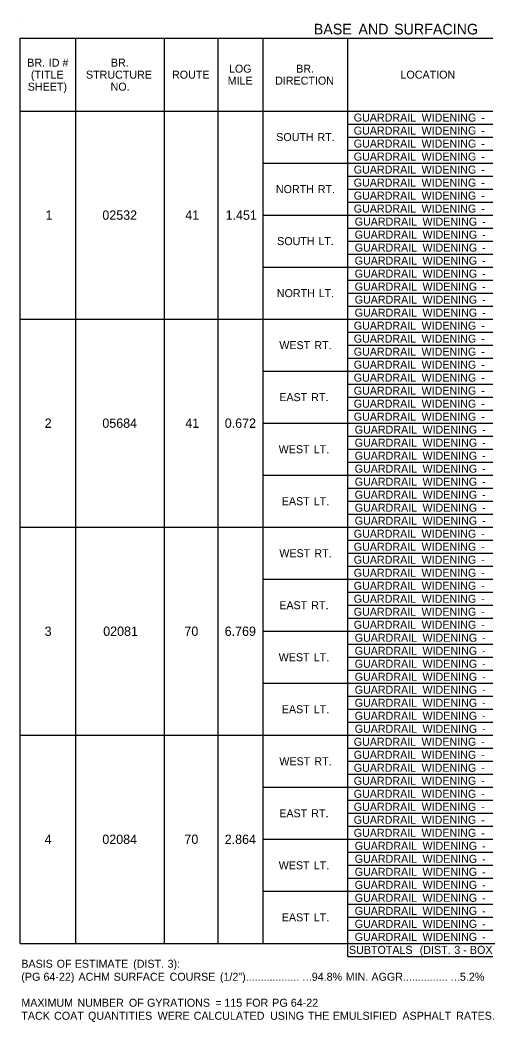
# Model space of a CAD drawing. Extents: x 544478 to 1930787, y -1948294 to 596640.
# Drawn here: x 550258 to 550607, y -1946930 to -1946179 of the extents above; entities that cross this region are included whole.
import ezdxf

# ---------------------------------------------------------------- set-up
doc = ezdxf.new("R2010")
doc.units = 0
doc.layers.add('Default', color=7, linetype='Continuous')

msp = doc.modelspace()

# ---------------------------------------------------------------- linework, layer by layer
at = {"layer": 'Default'}
for p, q in [((550257.56, -1946178.84), (550257.56, -1946178.84)), ((550257.56, -1946192.49), (551079.97, -1946192.49)), ((550257.56, -1946871.09), (550257.56, -1946192.49)), ((550299.48, -1946247.09), (550299.48, -1946192.49)), ((550299.48, -1946871.09), (550299.48, -1946192.49)), ((550365.78, -1946871.09), (550365.78, -1946192.49)), ((550406.25, -1946871.09), (550406.25, -1946192.49)), ((550439.88, -1946871.09), (550439.88, -1946192.49)), ((550503.26, -1946880.84), (550503.26, -1946192.49)), ((550257.56, -1946247.09), (551079.97, -1946247.09)), ((550503.26, -1946256.84), (551079.97, -1946256.84)), ((550503.26, -1946266.59), (551079.97, -1946266.59)), ((550503.26, -1946276.34), (551079.97, -1946276.34)), ((550439.88, -1946286.09), (550503.26, -1946286.09)), ((550503.26, -1946286.09), (551079.97, -1946286.09)), ((550503.26, -1946295.84), (551079.97, -1946295.84)), ((550503.26, -1946305.59), (551079.97, -1946305.59)), ((550503.26, -1946315.34), (551079.97, -1946315.34)), ((550439.88, -1946325.09), (550503.26, -1946325.09)), ((550503.26, -1946325.09), (551079.97, -1946325.09)), ((550503.26, -1946334.84), (551079.97, -1946334.84)), ((550503.26, -1946344.59), (551079.97, -1946344.59)), ((550503.26, -1946354.34), (551079.97, -1946354.34)), ((550439.88, -1946364.09), (550503.26, -1946364.09)), ((550503.26, -1946364.09), (550777.23, -1946364.09)), ((550503.26, -1946373.84), (551079.97, -1946373.84)), ((550503.26, -1946383.59), (550777.23, -1946383.59)), ((550503.26, -1946393.34), (550777.23, -1946393.34)), ((550257.56, -1946403.09), (551079.97, -1946403.09)), ((550503.26, -1946412.84), (551079.97, -1946412.84)), ((550503.26, -1946422.59), (551079.97, -1946422.59)), ((550503.26, -1946432.34), (551079.97, -1946432.34)), ((550439.88, -1946442.09), (550503.26, -1946442.09)), ((550503.26, -1946442.09), (551079.97, -1946442.09)), ((550503.26, -1946451.84), (551079.97, -1946451.84)), ((550503.26, -1946461.59), (551079.97, -1946461.59)), ((550503.26, -1946471.34), (551079.97, -1946471.34)), ((550439.88, -1946481.09), (550503.26, -1946481.09)), ((550503.26, -1946481.09), (551079.97, -1946481.09)), ((550503.26, -1946490.84), (551079.97, -1946490.84)), ((550503.26, -1946500.59), (551079.97, -1946500.59)), ((550503.26, -1946510.34), (551079.97, -1946510.34)), ((550439.88, -1946520.09), (550503.26, -1946520.09)), ((550503.26, -1946520.09), (550777.23, -1946520.09)), ((550503.26, -1946529.84), (551079.97, -1946529.84)), ((550503.26, -1946539.59), (550777.23, -1946539.59)), ((550503.26, -1946549.34), (550777.23, -1946549.34)), ((550257.56, -1946559.09), (551079.97, -1946559.09)), ((550503.26, -1946568.84), (551079.97, -1946568.84)), ((550503.26, -1946578.59), (551079.97, -1946578.59)), ((550503.26, -1946588.34), (551079.97, -1946588.34)), ((550439.88, -1946598.09), (550503.26, -1946598.09)), ((550503.26, -1946598.09), (551079.97, -1946598.09)), ((550503.26, -1946607.84), (551079.97, -1946607.84)), ((550503.26, -1946617.59), (551079.97, -1946617.59)), ((550503.26, -1946627.34), (551079.97, -1946627.34)), ((550439.88, -1946637.09), (550503.26, -1946637.09)), ((550503.26, -1946637.09), (551079.97, -1946637.09)), ((550503.26, -1946646.84), (551079.97, -1946646.84)), ((550503.26, -1946656.59), (551079.97, -1946656.59)), ((550503.26, -1946666.34), (551079.97, -1946666.34)), ((550439.88, -1946676.09), (550503.26, -1946676.09)), ((550503.26, -1946676.09), (550777.23, -1946676.09)), ((550503.26, -1946685.84), (551079.97, -1946685.84)), ((550503.26, -1946695.59), (550777.23, -1946695.59)), ((550503.26, -1946705.34), (550777.23, -1946705.34)), ((550257.56, -1946715.09), (551079.97, -1946715.09)), ((550503.26, -1946724.84), (551079.97, -1946724.84)), ((550503.26, -1946734.59), (551079.97, -1946734.59)), ((550503.26, -1946744.34), (551079.97, -1946744.34)), ((550439.88, -1946754.09), (550503.26, -1946754.09)), ((550503.26, -1946754.09), (551079.97, -1946754.09)), ((550503.26, -1946763.84), (551079.97, -1946763.84)), ((550503.26, -1946773.59), (551079.97, -1946773.59)), ((550503.26, -1946783.34), (551079.97, -1946783.34)), ((550439.88, -1946793.09), (550503.26, -1946793.09)), ((550503.26, -1946793.09), (551079.97, -1946793.09)), ((550503.26, -1946802.84), (551079.97, -1946802.84)), ((550503.26, -1946812.59), (551079.97, -1946812.59)), ((550503.26, -1946822.34), (551079.97, -1946822.34)), ((550439.88, -1946832.09), (550503.26, -1946832.09)), ((550503.26, -1946832.09), (550777.23, -1946832.09)), ((550503.26, -1946841.84), (551079.97, -1946841.84)), ((550503.26, -1946851.59), (550777.23, -1946851.59)), ((550503.26, -1946861.34), (550777.23, -1946861.34)), ((550257.56, -1946871.09), (551079.97, -1946871.09)), ((550503.26, -1946880.84), (550503.26, -1946871.09)), ((550503.26, -1946880.84), (551079.97, -1946880.84))]:
    msp.add_line(p, q, dxfattribs=at)

# ---------------------------------------------------------------- texts
for s, height, p in [('BASE', 8, (550477.82, -1946189.67)), (' AND', 8, (550508.32, -1946189.67)), (' SURFACING', 8, (550535.09, -1946189.67)), ('BR.', 6, (550263, -1946213.79)), (' ID', 6, (550276.86, -1946213.79)), (' #', 6, (550287.15, -1946213.79)), ('BR.', 6, (550325.7, -1946213.79)), ('(TITLE', 6, (550265.69, -1946222.79)), ('STRUCTURE', 6, (550306.99, -1946222.79)), ('ROUTE', 6, (550371.55, -1946222.79)), ('LOG', 6, (550414.24, -1946218.29)), ('BR.', 6, (550464.64, -1946218.29)), ('LOCATION', 6, (550542.89, -1946222.79)), ('SHEET)', 6, (550263.37, -1946231.79)), ('NO.', 6, (550325.47, -1946231.79)), ('MILE', 6, (550413.26, -1946227.29)), ('DIRECTION', 6, (550448.85, -1946227.29)), ('GUARDRAIL', 6, (550507.83, -1946254.97)), (' WIDENING', 6, (550556.45, -1946254.97)), (' -', 6, (550601.09, -1946254.97)), ('SOUTH', 6, (550449.69, -1946269.59)), (' RT.', 6, (550478.36, -1946269.59)), ('GUARDRAIL', 6, (550507.83, -1946264.72)), (' WIDENING', 6, (550556.45, -1946264.72)), (' -', 6, (550601.09, -1946264.72)), ('GUARDRAIL', 6, (550507.83, -1946274.47)), (' WIDENING', 6, (550556.45, -1946274.47)), ('GUARDRAIL', 6, (550507.83, -1946284.22)), (' WIDENING', 6, (550556.45, -1946284.22)), (' -', 6, (550601.09, -1946274.47)), (' -', 6, (550601.09, -1946284.22)), ('GUARDRAIL', 6, (550507.83, -1946293.97)), (' WIDENING', 6, (550556.45, -1946293.97)), (' -', 6, (550601.09, -1946293.97)), ('GUARDRAIL', 6, (550507.83, -1946303.72)), (' WIDENING', 6, (550556.45, -1946303.72)), (' -', 6, (550601.09, -1946303.72)), ('NORTH', 6, (550449.46, -1946308.59)), (' RT.', 6, (550478.59, -1946308.59)), ('GUARDRAIL', 6, (550507.83, -1946313.47)), (' WIDENING', 6, (550556.45, -1946313.47)), (' -', 6, (550601.09, -1946313.47)), ('1', 7, (550276.7, -1946328.59)), ('02532', 7, (550319.3, -1946328.59)), ('41', 7, (550381.48, -1946328.59)), ('1.451', 7, (550411.73, -1946328.59)), ('GUARDRAIL', 6, (550507.83, -1946323.22)), (' WIDENING', 6, (550556.45, -1946323.22)), (' -', 6, (550601.09, -1946323.22)), ('GUARDRAIL', 6, (550508.53, -1946332.97)), (' WIDENING', 6, (550557.14, -1946332.97)), (' -', 6, (550601.79, -1946332.97)), ('GUARDRAIL', 6, (550508.53, -1946342.72)), (' WIDENING', 6, (550557.14, -1946342.72)), ('SOUTH', 6, (550450.38, -1946347.59)), (' LT.', 6, (550479.05, -1946347.59)), ('GUARDRAIL', 6, (550508.53, -1946352.47)), (' WIDENING', 6, (550557.14, -1946352.47)), (' -', 6, (550601.79, -1946342.72)), (' -', 6, (550601.79, -1946352.47)), ('GUARDRAIL', 6, (550508.53, -1946362.22)), (' WIDENING', 6, (550557.14, -1946362.22)), (' -', 6, (550601.79, -1946362.22)), ('GUARDRAIL', 6, (550508.53, -1946371.97)), (' WIDENING', 6, (550557.14, -1946371.97)), ('GUARDRAIL', 6, (550508.53, -1946381.72)), (' WIDENING', 6, (550557.14, -1946381.72)), (' -', 6, (550601.79, -1946371.97)), ('NORTH', 6, (550450.15, -1946386.59)), (' LT.', 6, (550479.28, -1946386.59)), (' -', 6, (550601.79, -1946381.72)), ('GUARDRAIL', 6, (550508.53, -1946391.47)), (' WIDENING', 6, (550557.14, -1946391.47)), (' -', 6, (550601.79, -1946391.47)), ('GUARDRAIL', 6, (550508.53, -1946401.22)), (' WIDENING', 6, (550557.14, -1946401.22)), (' -', 6, (550601.79, -1946401.22)), ('GUARDRAIL', 6, (550507.83, -1946410.97)), (' WIDENING', 6, (550556.45, -1946410.97)), (' -', 6, (550601.09, -1946410.97)), ('WEST', 6, (550452, -1946425.59)), (' RT.', 6, (550476.05, -1946425.59)), ('GUARDRAIL', 6, (550507.83, -1946420.72)), (' WIDENING', 6, (550556.45, -1946420.72)), (' -', 6, (550601.09, -1946420.72)), ('GUARDRAIL', 6, (550507.83, -1946430.47)), (' WIDENING', 6, (550556.45, -1946430.47)), (' -', 6, (550601.09, -1946430.47)), ('GUARDRAIL', 6, (550507.83, -1946440.22)), (' WIDENING', 6, (550556.45, -1946440.22)), ('GUARDRAIL', 6, (550507.83, -1946449.97)), (' WIDENING', 6, (550556.45, -1946449.97)), (' -', 6, (550601.09, -1946440.22)), (' -', 6, (550601.09, -1946449.97)), ('EAST', 6, (550451.99, -1946464.59)), (' RT.', 6, (550473.72, -1946464.59)), ('GUARDRAIL', 6, (550507.83, -1946459.72)), (' WIDENING', 6, (550556.45, -1946459.72)), (' -', 6, (550601.09, -1946459.72)), ('GUARDRAIL', 6, (550507.83, -1946469.47)), (' WIDENING', 6, (550556.45, -1946469.47)), ('GUARDRAIL', 6, (550507.83, -1946479.22)), (' WIDENING', 6, (550556.45, -1946479.22)), (' -', 6, (550601.09, -1946469.47)), ('2', 7, (550276.06, -1946484.59)), ('05684', 7, (550319.28, -1946484.59)), ('41', 7, (550381.48, -1946484.59)), ('0.672', 7, (550411.09, -1946484.59)), (' -', 6, (550601.09, -1946479.22)), ('GUARDRAIL', 6, (550508.53, -1946488.97)), (' WIDENING', 6, (550557.14, -1946488.97)), (' -', 6, (550601.79, -1946488.97)), ('GUARDRAIL', 6, (550508.53, -1946498.72)), (' WIDENING', 6, (550557.14, -1946498.72)), (' -', 6, (550601.79, -1946498.72)), ('WEST', 6, (550451.53, -1946503.59)), (' LT.', 6, (550475.58, -1946503.59)), ('GUARDRAIL', 6, (550508.53, -1946508.47)), (' WIDENING', 6, (550557.14, -1946508.47)), (' -', 6, (550601.79, -1946508.47)), ('GUARDRAIL', 6, (550508.53, -1946518.22)), (' WIDENING', 6, (550557.14, -1946518.22)), (' -', 6, (550601.79, -1946518.22)), ('GUARDRAIL', 6, (550508.53, -1946527.97)), (' WIDENING', 6, (550557.14, -1946527.97)), (' -', 6, (550601.79, -1946527.97)), ('GUARDRAIL', 6, (550508.53, -1946537.72)), (' WIDENING', 6, (550557.14, -1946537.72)), ('EAST', 6, (550453.85, -1946542.59)), (' LT.', 6, (550475.59, -1946542.59)), ('GUARDRAIL', 6, (550508.53, -1946547.47)), (' WIDENING', 6, (550557.14, -1946547.47)), (' -', 6, (550601.79, -1946537.72)), (' -', 6, (550601.79, -1946547.47)), ('GUARDRAIL', 6, (550508.53, -1946557.22)), (' WIDENING', 6, (550557.14, -1946557.22)), (' -', 6, (550601.79, -1946557.22)), ('GUARDRAIL', 6, (550507.83, -1946566.97)), (' WIDENING', 6, (550556.45, -1946566.97)), ('GUARDRAIL', 6, (550507.83, -1946576.72)), (' WIDENING', 6, (550556.45, -1946576.72)), (' -', 6, (550601.09, -1946566.97)), ('WEST', 6, (550452, -1946581.59)), (' RT.', 6, (550476.05, -1946581.59)), (' -', 6, (550601.09, -1946576.72)), ('GUARDRAIL', 6, (550507.83, -1946586.47)), (' WIDENING', 6, (550556.45, -1946586.47)), (' -', 6, (550601.09, -1946586.47)), ('GUARDRAIL', 6, (550507.83, -1946596.22)), (' WIDENING', 6, (550556.45, -1946596.22)), (' -', 6, (550601.09, -1946596.22)), ('GUARDRAIL', 6, (550507.83, -1946605.97)), (' WIDENING', 6, (550556.45, -1946605.97)), (' -', 6, (550601.09, -1946605.97)), ('EAST', 6, (550451.99, -1946620.59)), (' RT.', 6, (550473.72, -1946620.59)), ('GUARDRAIL', 6, (550507.83, -1946615.72)), (' WIDENING', 6, (550556.45, -1946615.72)), (' -', 6, (550601.09, -1946615.72)), ('GUARDRAIL', 6, (550507.83, -1946625.47)), (' WIDENING', 6, (550556.45, -1946625.47)), (' -', 6, (550601.09, -1946625.47)), ('GUARDRAIL', 6, (550507.83, -1946635.22)), (' WIDENING', 6, (550556.45, -1946635.22)), ('3', 7, (550276.03, -1946640.59)), ('02081', 7, (550319.94, -1946640.59)), ('70', 7, (550380.81, -1946640.59)), ('6.769', 7, (550411.05, -1946640.59)), ('GUARDRAIL', 6, (550508.53, -1946644.97)), (' WIDENING', 6, (550557.14, -1946644.97)), (' -', 6, (550601.09, -1946635.22)), (' -', 6, (550601.79, -1946644.97)), ('WEST', 6, (550451.53, -1946659.59)), (' LT.', 6, (550475.58, -1946659.59)), ('GUARDRAIL', 6, (550508.53, -1946654.72)), (' WIDENING', 6, (550557.14, -1946654.72)), (' -', 6, (550601.79, -1946654.72)), ('GUARDRAIL', 6, (550508.53, -1946664.47)), (' WIDENING', 6, (550557.14, -1946664.47)), (' -', 6, (550601.79, -1946664.47)), ('GUARDRAIL', 6, (550508.53, -1946674.22)), (' WIDENING', 6, (550557.14, -1946674.22)), (' -', 6, (550601.79, -1946674.22)), ('GUARDRAIL', 6, (550508.53, -1946683.97)), (' WIDENING', 6, (550557.14, -1946683.97)), (' -', 6, (550601.79, -1946683.97)), ('GUARDRAIL', 6, (550508.53, -1946693.72)), (' WIDENING', 6, (550557.14, -1946693.72)), (' -', 6, (550601.79, -1946693.72)), ('EAST', 6, (550453.85, -1946698.59)), (' LT.', 6, (550475.59, -1946698.59)), ('GUARDRAIL', 6, (550508.53, -1946703.47)), (' WIDENING', 6, (550557.14, -1946703.47)), (' -', 6, (550601.79, -1946703.47)), ('GUARDRAIL', 6, (550508.53, -1946713.22)), (' WIDENING', 6, (550557.14, -1946713.22)), (' -', 6, (550601.79, -1946713.22)), ('GUARDRAIL', 6, (550507.83, -1946722.97)), (' WIDENING', 6, (550556.45, -1946722.97)), (' -', 6, (550601.09, -1946722.97)), ('GUARDRAIL', 6, (550507.83, -1946732.72)), (' WIDENING', 6, (550556.45, -1946732.72)), ('WEST', 6, (550452, -1946737.59)), (' RT.', 6, (550476.05, -1946737.59)), ('GUARDRAIL', 6, (550507.83, -1946742.47)), (' WIDENING', 6, (550556.45, -1946742.47)), (' -', 6, (550601.09, -1946732.72)), (' -', 6, (550601.09, -1946742.47)), ('GUARDRAIL', 6, (550507.83, -1946752.22)), (' WIDENING', 6, (550556.45, -1946752.22)), (' -', 6, (550601.09, -1946752.22)), ('GUARDRAIL', 6, (550507.83, -1946761.97)), (' WIDENING', 6, (550556.45, -1946761.97)), (' -', 6, (550601.09, -1946761.97)), ('GUARDRAIL', 6, (550507.83, -1946771.72)), (' WIDENING', 6, (550556.45, -1946771.72)), ('EAST', 6, (550451.99, -1946776.59)), (' RT.', 6, (550473.72, -1946776.59)), (' -', 6, (550601.09, -1946771.72)), ('GUARDRAIL', 6, (550507.83, -1946781.47)), (' WIDENING', 6, (550556.45, -1946781.47)), (' -', 6, (550601.09, -1946781.47)), ('4', 7, (550276.04, -1946796.59)), ('02084', 7, (550319.28, -1946796.59)), ('70', 7, (550380.81, -1946796.59)), ('2.864', 7, (550411.07, -1946796.59)), ('GUARDRAIL', 6, (550507.83, -1946791.22)), (' WIDENING', 6, (550556.45, -1946791.22)), (' -', 6, (550601.09, -1946791.22)), ('GUARDRAIL', 6, (550508.53, -1946800.97)), (' WIDENING', 6, (550557.14, -1946800.97)), ('GUARDRAIL', 6, (550508.53, -1946810.72)), (' WIDENING', 6, (550557.14, -1946810.72)), (' -', 6, (550601.79, -1946800.97)), ('WEST', 6, (550451.53, -1946815.59)), (' LT.', 6, (550475.58, -1946815.59)), (' -', 6, (550601.79, -1946810.72)), ('GUARDRAIL', 6, (550508.53, -1946820.47)), (' WIDENING', 6, (550557.14, -1946820.47)), (' -', 6, (550601.79, -1946820.47)), ('GUARDRAIL', 6, (550508.53, -1946830.22)), (' WIDENING', 6, (550557.14, -1946830.22)), ('GUARDRAIL', 6, (550508.53, -1946839.97)), (' WIDENING', 6, (550557.14, -1946839.97)), (' -', 6, (550601.79, -1946830.22)), (' -', 6, (550601.79, -1946839.97)), ('EAST', 6, (550453.85, -1946854.59)), (' LT.', 6, (550475.59, -1946854.59)), ('GUARDRAIL', 6, (550508.53, -1946849.72)), (' WIDENING', 6, (550557.14, -1946849.72)), (' -', 6, (550601.79, -1946849.72)), ('GUARDRAIL', 6, (550508.53, -1946859.47)), (' WIDENING', 6, (550557.14, -1946859.47)), (' -', 6, (550601.79, -1946859.47)), ('GUARDRAIL', 6, (550508.53, -1946869.22)), (' WIDENING', 6, (550557.14, -1946869.22)), (' -', 6, (550601.79, -1946869.22)), ('SUBTOTALS', 6, (550504.23, -1946878.97)), (' (DIST.', 6, (550555.06, -1946878.97)), (' 3', 6, (550581.03, -1946878.97)), (' -', 6, (550587.65, -1946878.97)), (' BOX', 6, (550592.71, -1946878.97)), ('BASIS', 6, (550258.53, -1946889.39)), (' OF', 6, (550282.8, -1946889.39)), (' ESTIMATE', 6, (550296.38, -1946889.39)), (' (DIST.', 6, (550340.19, -1946889.39)), (' 3):', 6, (550366, -1946889.39)), ('(PG', 6, (550258.53, -1946899.14)), (' 64-22)', 6, (550272.91, -1946899.14)), (' ACHM', 6, (550299.16, -1946899.14)), (' SURFACE', 6, (550325.54, -1946899.14)), (' COURSE', 6, (550367.49, -1946899.14)), (' (1/2")..................', 6, (550405.24, -1946899.14)), ('94.8%', 6, (550476.34, -1946899.14)), (' MIN.', 6, (550499.58, -1946899.14)), (' AGGR...............', 6, (550518.87, -1946899.14)), ('5.2%', 6, (550587.47, -1946899.14)), ('…', 6, (550468.94, -1946899.14)), ('…', 6, (550580.07, -1946899.14)), ('MAXIMUM', 6, (550258.53, -1946918.64)), (' NUMBER', 6, (550298.42, -1946918.64)), (' OF', 6, (550336.97, -1946918.64)), (' GYRATIONS', 6, (550350.56, -1946918.64)), (' =', 6, (550401.83, -1946918.64)), (' 115', 6, (550408.58, -1946918.64)), (' FOR', 6, (550424.55, -1946918.64)), (' PG', 6, (550444.47, -1946918.64)), (' 64-22', 6, (550458.38, -1946918.64)), ('TACK', 6, (550258.53, -1946928.39)), (' COAT', 6, (550280.88, -1946928.39)), (' QUANTITIES', 6, (550306.33, -1946928.39)), (' WERE', 6, (550358.53, -1946928.39)), (' CALCULATED', 6, (550385.56, -1946928.39)), (' USING', 6, (550442.88, -1946928.39)), (' THE', 6, (550471.23, -1946928.39)), (' EMULSIFIED', 6, (550489.88, -1946928.39)), (' ASPHALT', 6, (550542.07, -1946928.39)), (' RATES.', 6, (550582.44, -1946928.39))]:
    msp.add_text(s, height=height, dxfattribs=at).set_placement(p)

doc.saveas('drawing.dxf')
